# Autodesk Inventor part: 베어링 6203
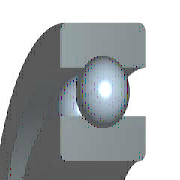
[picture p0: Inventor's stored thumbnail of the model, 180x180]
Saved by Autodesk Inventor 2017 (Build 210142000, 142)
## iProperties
Created: 2012-02
Part Number: 베어링 6203
Material: 강철, 연강
Description: 깊은 그루브 볼 베어링
Document SubType Name: Modeling
Standard: KS B 2023
Designer: mduedu
Standards Organization: KS
Language: ko-KR
Size Designation: 6203 - 17 x 40 x 12
Categories: <MemberInstance><Categories><Category DisplayName="샤프트 부품" InternalName="7f7aeb1f-a693-4053-b835-cee3144e0d98" Mnemonic="SHFT"><Category DisplayName="베어링" Inter
Density: 1 g/cm^3
Appearance: Yellow
IsCustomPart: 1
Author: mduedu
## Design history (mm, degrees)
sketch "스케치" dims "d0" = 5.98 (= -0.26 x WD + 0.26 x BD)
  geometry: L1 (3.01, 14.25)-(8.99, 14.25); L2 (6, 14.25)-(6, 11.26); L3 (6, 14.25)-(6, 17.24); L4 (3.778, 12.249)-(0, 12.249); L5 (0, 8.5)-(12, 8.5); L6 (3.778, 16.251)-(0, 16.251); L7 (0, 20)-(12, 20); L8 (12, 8.5)-(12, 12.249); L9 (8.222, 12.249)-(12, 12.249); L10 (8.222, 16.251)-(12, 16.251); L11 (12, 20)-(12, 16.251); L12 (-1.4, 0)-(8.4, 0) reference; L13 (0, -0.3)-(0, 5.3) reference
  constraints: 22 end point, 4 point on line, 2 collinear, 2 perpendicular, 2 symmetric about line, 1 midpoint, 1 parallel, 14 other
  dimensions: "d9" = 17 diameter of L5 L12 (= WD); "d11" = 40 diameter of L7 L12 (= BD); "d12" = 12 distance between parallel lines of L8 L13 (= KB); "d13" = 24.498 diameter of L9 L12 (= 0.326 x BD + 0.674 x WD)
revolve "본체" stored, may be unused: angle "d6" = 90 deg
revolve "볼" stored, may be unused: angle "d7" = 90 deg
pattern_circular "IDS_ARRAYBALL[SIMPL:T]" dims angle "d3" = 360 deg
body "Solid1"
fillet "모깎기1" dims "d1" = 0.6 (= KRS)
other parameters: "WD" = 17 [user parameter; used in 5 equation terms], "BD" = 40 [user parameter; used in 5 equation terms], "KB" = 12 [user parameter; used in 1 equation term], "KRS" = 0.6 [user parameter; used in 1 equation term], "d4" = 0, "d5" = 0, "d8" = 0, "d14" = 0, "d15" = 0, "BBA" = 0 [user parameter], "BC0" = 4750000 [user parameter], "BC" = 9560000 [user parameter], "WR" = 8.5 (= 0.5 x WD) [user parameter]
